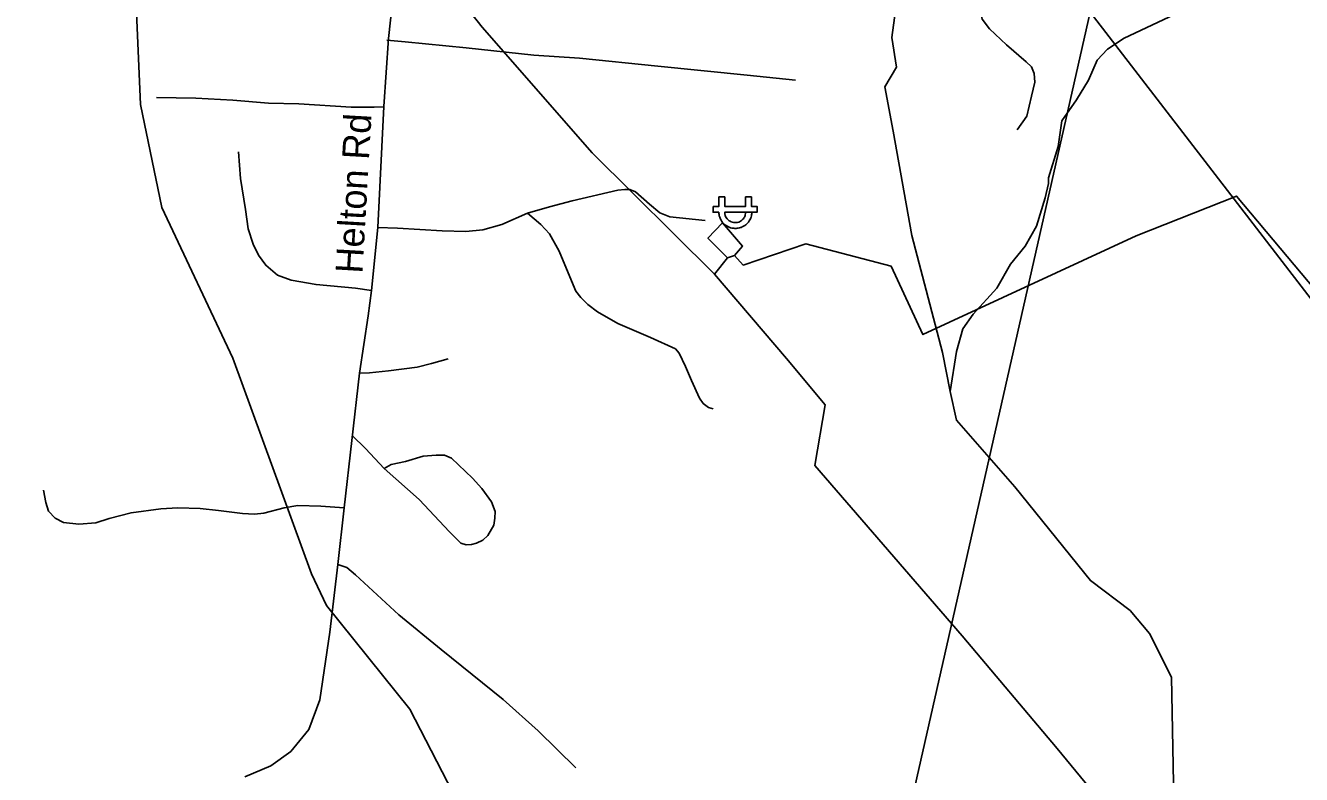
# Model space of a CAD drawing. Extents: x 1159738 to 1321356, y 736314 to 882035.
# Drawn here: x 1265994 to 1269553, y 756175 to 758264 of the extents above; entities that cross this region are included whole.
import ezdxf

# ---------------------------------------------------------------- set-up
doc = ezdxf.new("R2010")
doc.units = 0
for name, color, linetype in [('Exist Boundary Political City Limit New', 7, 'Continuous'), ('Exist Hydrographic Creek Single Shore', 7, 'Continuous'), ('Exist Hydrographic Misc Water Feature', 7, 'Continuous'), ('Exist Road Non-System Type 51', 7, 'Continuous'), ('Exist Road Non-System Type 51 Label', 7, 'Continuous'), ('Exist Utilities Electrical Power Substation CELL', 7, 'Continuous'), ('Exist Utilities Electrical Transmission Line', 7, 'Continuous'), ('Map Preparation Boundary City Limit Buffer Line', 7, 'Continuous')]:
    doc.layers.add(name, color=color, linetype=linetype)

msp = doc.modelspace()

# ---------------------------------------------------------------- linework, layer by layer
at = {"layer": 'Exist Boundary Political City Limit New'}
msp.add_lwpolyline([(1269878.7, 761546.2), (1269539.2, 761533.3), (1269537.9, 760315.4), (1270212.7, 760078.9), (1270689.8, 759833.7), (1271412.1, 759421), (1271201.9, 759086.7), (1270810.7, 759073.8), (1270531, 758857.5), (1270128.2, 757680.8), (1269952, 757629.2), (1269633.9, 757431.4), (1268964.2, 758300.9), (1268311.3, 755418.1)], dxfattribs=at)
at = {"layer": 'Exist Hydrographic Creek Single Shore'}
for points in [[(1268591.4, 757163.5), (1268573.2, 757243.1), (1268552.1, 757351.7), (1268466.1, 757678.1), (1268414.6, 757968.8), (1268391.2, 758092.7), (1268423.2, 758147.5), (1268410.9, 758230.9), (1268428.1, 758361.9), (1268374, 758538.2), (1268274.6, 758712.2), (1268196, 758881.3), (1268124.7, 758974.3), (1268122.6, 759014.8), (1268114.9, 759098.2), (1268011.8, 759164.9), (1267918.4, 759238.7), (1267778.4, 759541.3), (1267719.5, 759870.1), (1267762.6, 760292.4), (1267683.5, 760461.3), (1267661.6, 760586.6)], [(1267200.7, 756095.5), (1267065.6, 756357.5), (1266833.9, 756646.5), (1266791.4, 756734.2), (1266572.6, 757335.7), (1266374.6, 757756.6), (1266314.6, 758043.4), (1266293.6, 758536.2), (1266262.6, 758635.2), (1266192, 758727.9)], [(1269305.7, 755551), (1269199.3, 756003.2), (1269190.7, 756446.3), (1269129.3, 756567.8), (1269075.3, 756632.2), (1268964.7, 756715.5), (1268753.5, 756977.6), (1268591.4, 757163.5)]]:
    msp.add_lwpolyline(points, dxfattribs=at)
at = {"layer": 'Exist Hydrographic Misc Water Feature'}
msp.add_lwpolyline([(1268573.2, 757243.1), (1268590.6, 757354.4), (1268608.3, 757417.9), (1268637.5, 757458.8), (1268703.5, 757531.1), (1268741.4, 757598), (1268782.8, 757648.8), (1268814.3, 757703.9), (1268838.5, 757783.2), (1268847.6, 757822.9), (1268848, 757838.9), (1268874.5, 757926.2), (1268884.5, 757997.8), (1268926.2, 758056.6), (1268959.7, 758111.6), (1268983.2, 758167), (1269012.1, 758198.1), (1269058.9, 758228.8), (1269215, 758302.3)], dxfattribs=at)
at = {"layer": 'Exist Road Non-System Type 51'}
for points in [[(1268780.5, 758544), (1268768.6, 758528.5), (1268732.2, 758464), (1268695.5, 758410.6), (1268671.5, 758356.7), (1268661, 758335.4), (1268658, 758316.9), (1268658, 758301.3), (1268662.5, 758281.4), (1268683.4, 758254.5), (1268730.5, 758209.7), (1268785.7, 758162.9), (1268800.7, 758148.7), (1268808.1, 758130.2), (1268809.6, 758106.1), (1268800.7, 758066.4), (1268787.2, 758011), (1268760.3, 757972.7)], [(1267032.8, 758467.2), (1267006.3, 758227.2), (1266993.4, 758037.6), (1266976.9, 757700.4), (1266959.5, 757524.8), (1266949.3, 757454.2), (1266926, 757294.1), (1266882.9, 756918.8), (1266865, 756760.2), (1266842.8, 756571.5), (1266815.3, 756382.9), (1266783.9, 756300.2), (1266733.6, 756238.9), (1266678, 756198.8), (1266605.7, 756167.9)], [(1267001.5, 758222.7), (1267052.8, 758218.2), (1267222.8, 758201.5), (1267412, 758181.6), (1267539.6, 758172.6), (1267757.4, 758150.2), (1268006.6, 758125.8), (1268141.7, 758111.1)], [(1266359.6, 758063.1), (1266468.6, 758061.2), (1266572.5, 758055.4), (1266671.3, 758047.7), (1266756.6, 758045.8), (1266902.4, 758036.2), (1266966.5, 758036.2), (1266991.6, 758036.8)], [(1266959.5, 757524.8), (1266914.6, 757531.2), (1266804.3, 757541.5), (1266735, 757553.7), (1266696.6, 757567.8), (1266663.9, 757595.4), (1266644, 757623.6), (1266629.2, 757653.8), (1266615.1, 757696.8), (1266607.6, 757751), (1266593.5, 757837.6), (1266587.7, 757911.4)], [(1267394.1, 757740.4), (1267455.4, 757757.8), (1267519.3, 757774.8), (1267646, 757804.3), (1267665.7, 757806.5), (1267680, 757806.1), (1267695.2, 757799.8), (1267734.2, 757765.4), (1267763.7, 757741.2), (1267791.4, 757730.4), (1267890, 757720.3)], [(1266976.9, 757700.4), (1267032, 757698.8), (1267155.9, 757691.6), (1267222.5, 757688.9), (1267269.5, 757693.9), (1267323.1, 757708.6), (1267394.1, 757740.4)], [(1267394.1, 757740.4), (1267431.9, 757708.6), (1267455.6, 757683.1), (1267482.4, 757634.3), (1267511.9, 757563.2), (1267529.3, 757523.2), (1267542.7, 757504.9), (1267562.9, 757485.6), (1267589.7, 757465.1), (1267646.5, 757432.8), (1267737.3, 757393.4), (1267806.8, 757362.4), (1267817.5, 757350.3), (1267835.4, 757312.7), (1267852, 757273.4), (1267873.9, 757224.1), (1267884.6, 757209.8), (1267899.4, 757198.6), (1267911.9, 757194.6)], [(1266926, 757294.1), (1266953.6, 757295.4), (1267006.2, 757300.5), (1267086.4, 757311.4), (1267126.8, 757321.1), (1267172.9, 757333.9)], [(1266905.2, 757120.2), (1266942.1, 757083.8), (1266994.3, 757028.5)], [(1266994.3, 757028.5), (1267092.5, 756941.4), (1267176.4, 756852), (1267208.6, 756820.2), (1267222.9, 756815.6), (1267238.3, 756816.1), (1267251.6, 756819.7), (1267270, 756828.9), (1267283.3, 756841.2), (1267300.2, 756869.9), (1267303.3, 756889.9), (1267304.3, 756908.3), (1267294.1, 756935), (1267267, 756972.9), (1267240.9, 757001), (1267182, 757057.4), (1267163.1, 757065.1), (1267139, 757065.6), (1267103.2, 757062.5), (1267054, 757048.2), (1267013.6, 757039.5), (1266994.3, 757028.5)], [(1266882.9, 756918.8), (1266817.7, 756923.4), (1266753.5, 756925.1), (1266715.2, 756918.3), (1266658.5, 756903.4), (1266632.7, 756901.1), (1266599.5, 756902.8), (1266532.5, 756910.8), (1266481.5, 756917.1), (1266419.1, 756918.3), (1266371.8, 756916), (1266288.2, 756905.1), (1266227.5, 756889), (1266189.7, 756877), (1266142.2, 756873), (1266099.5, 756877.6), (1266076.6, 756889.6), (1266057.7, 756909.6), (1266050.3, 756933.7), (1266044.5, 756967.5)], [(1266865, 756760.2), (1266890.4, 756752.4), (1266914.2, 756732), (1267035.3, 756620.2), (1267153.7, 756523.9), (1267326.5, 756384.2), (1267423.8, 756296.8), (1267529.2, 756193)]]:
    msp.add_lwpolyline(points, dxfattribs=at)
at = {"layer": 'Exist Utilities Electrical Power Substation CELL'}
msp.add_lwpolyline([(1267912.1, 757759.2), (1267928.1, 757759.2), (1267928.1, 757785.6), (1267944.4, 757785.6), (1267944.4, 757759.2), (1268002.5, 757759.2), (1268002.5, 757785.6), (1268018.7, 757785.6), (1268018.7, 757759.2), (1268034.7, 757759.2), (1268034.7, 757743.2), (1268018.7, 757743.2), (1268002.5, 757743.2), (1267944.4, 757743.2), (1267944.9, 757738.2), (1267945.9, 757733.8), (1267947.9, 757729.2), (1267950.9, 757724.8), (1267954.8, 757720.8), (1267956.9, 757719.2), (1267959.4, 757717.8), (1267962.5, 757716.1), (1267965.9, 757715), (1267969.8, 757714.2), (1267972.8, 757714), (1267976.3, 757714.1), (1267980.2, 757714.7), (1267983.7, 757715.7), (1267986.1, 757716.7), (1267988.8, 757718.2), (1267991.6, 757720.1), (1267994.2, 757722.4), (1267996.4, 757724.9), (1267998.1, 757727.2), (1267999.2, 757729.2), (1268000.4, 757731.4), (1268001.5, 757734.3), (1268001.9, 757736.2), (1268002.5, 757739.2), (1268002.7, 757741.5), (1268002.9, 757743.2), (1268020.6, 757743.2), (1268020.3, 757740.4), (1268020, 757738.2), (1268019.6, 757735.5), (1268018.9, 757732.8), (1268018.1, 757729.7), (1268017.2, 757727.1), (1268016.2, 757724.5), (1268014.7, 757721.6), (1268012.8, 757718.7), (1268010.7, 757715.7), (1268008.6, 757713.2), (1268006.4, 757711), (1268003.4, 757708.3), (1268000.3, 757706), (1267996.9, 757703.9), (1267993.3, 757702.1), (1267990.5, 757700.9), (1267988, 757700.1), (1267985.4, 757699.4), (1267982.3, 757698.7), (1267979.2, 757698.3), (1267976.4, 757698), (1267972.8, 757698), (1267970.3, 757698.2), (1267967.5, 757698.5), (1267964.6, 757699.1), (1267960.6, 757700), (1267956.5, 757701.5), (1267952.9, 757703.2), (1267949.9, 757704.9), (1267946.5, 757707.1), (1267943.9, 757709.3), (1267942.4, 757710.6), (1267940.3, 757712.6), (1267938.7, 757714.5), (1267936.5, 757717.2), (1267934.3, 757720.7), (1267932.7, 757723.7), (1267931.4, 757726.5), (1267930.5, 757729.1), (1267929.2, 757733.3), (1267928.5, 757736.9), (1267928.1, 757740), (1267927.9, 757743.2), (1267912.1, 757743.2)], close=True, dxfattribs=at)
at = {"layer": 'Exist Utilities Electrical Transmission Line'}
for points in [[(1260071.3, 766656.1), (1260559, 766155.8), (1260895.8, 765818.2), (1261306.3, 765401), (1262050.5, 764660.7), (1262241.8, 764477.3), (1262584.8, 764023.8), (1262894.9, 763624.6), (1263352, 763026.8), (1264106.6, 762036.4), (1264464.1, 761610.6), (1264877.2, 761103.9), (1265877.9, 759872.5), (1265970.7, 759775.2), (1266388.3, 759310.1), (1266775.8, 758837.4), (1266960.8, 758648.2), (1267267.8, 758259.1), (1267574.2, 757908.8), (1267916.1, 757570.1), (1267951.8, 757615.6)], [(1267971.9, 757622.6), (1267995.8, 757595.8), (1268170.4, 757655), (1268408.6, 757592.8), (1268497.4, 757401.8), (1269092.3, 757677.2), (1269372.6, 757788), (1269655.2, 757451.8), (1270041.6, 756995.4), (1270394.8, 756957.7), (1271066.5, 756920.6)], [(1267971.9, 757622.6), (1267994, 757648.8), (1267937.8, 757713.1), (1267897.6, 757670.9), (1267951.8, 757615.6), (1267971.9, 757622.6)], [(1267916.1, 757570.1), (1268117, 757334.8), (1268224.5, 757205.5), (1268196, 757037), (1268606.9, 756561.4), (1268872.3, 756247.6), (1269080.3, 755994.6), (1269439.5, 755573.1), (1269634, 755464.1), (1269829.1, 755190.5), (1269952.9, 754977), (1270023.6, 754897.8)]]:
    msp.add_lwpolyline(points, dxfattribs=at)
at = {"layer": 'Map Preparation Boundary City Limit Buffer Line'}
msp.add_lwpolyline([(1269878.7, 761546.2), (1269539.2, 761533.3), (1269537.9, 760315.4), (1270212.7, 760078.9), (1270689.8, 759833.7), (1271412.1, 759421), (1271201.9, 759086.7), (1270810.7, 759073.8), (1270531, 758857.5), (1270128.2, 757680.8), (1269952, 757629.2), (1269633.9, 757431.4), (1268964.2, 758300.9), (1268311.3, 755418.1)], dxfattribs=at)

# ---------------------------------------------------------------- texts
at = {"layer": 'Exist Road Non-System Type 51 Label'}
msp.add_text('Helton Rd', height=75, rotation=86.696, dxfattribs=at).set_placement((1266933.5, 757570.9))

doc.saveas('drawing.dxf')
